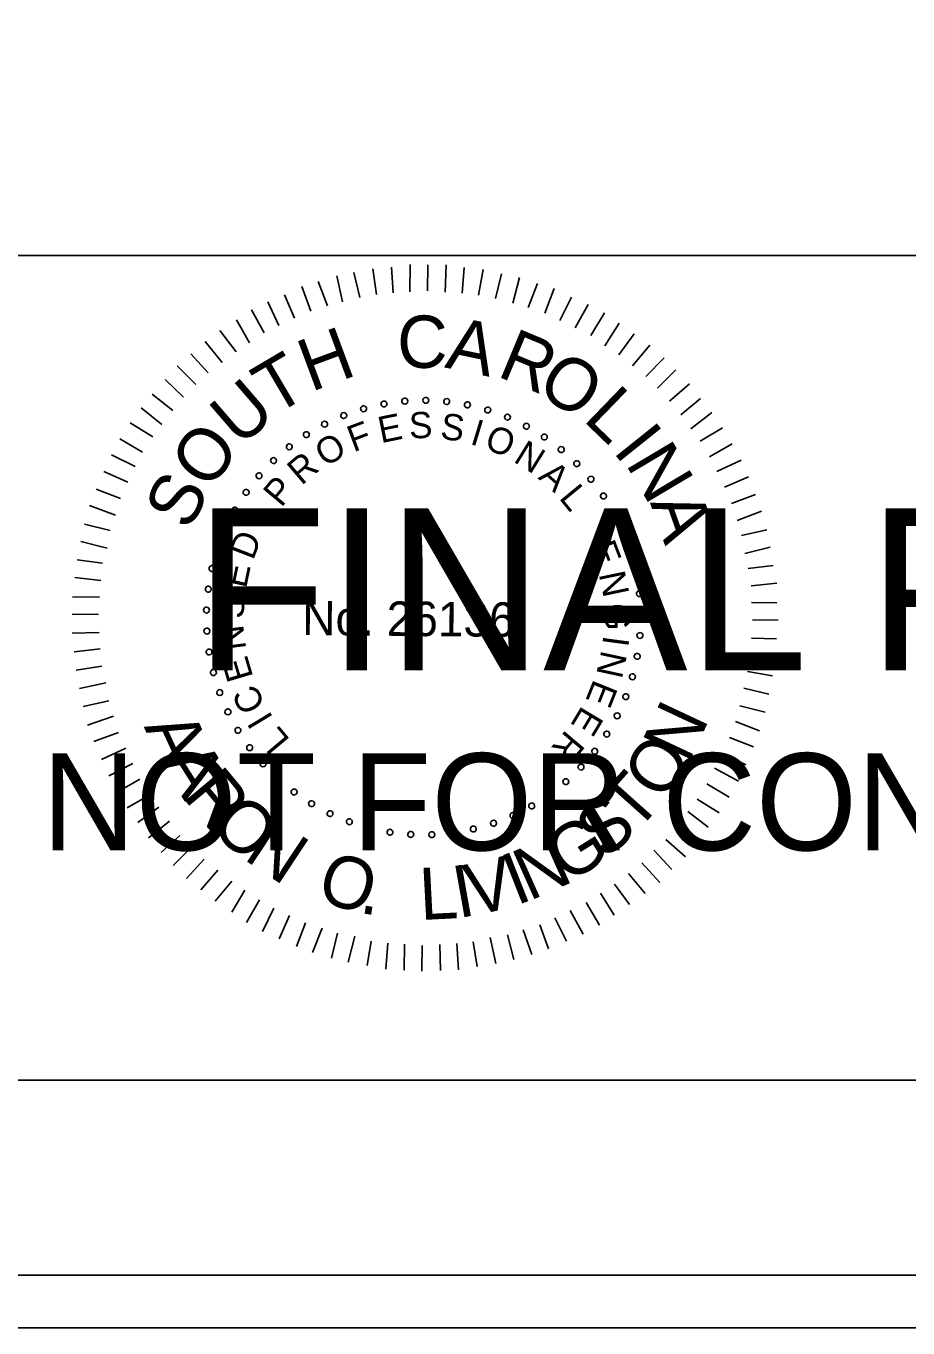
# Model space of a CAD drawing. Extents: x 967 to 1326, y 964 to 3704.
# Drawn here: x 1170.56 to 1189.3, y 3203.72 to 3231.36 of the extents above; entities that cross this region are included whole.
import ezdxf

# ---------------------------------------------------------------- set-up
doc = ezdxf.new("R2010")
doc.units = 0
for name, color, linetype in [('RD_SHT_Bndy', 7, 'Continuous'), ('RD_SHT_IplotShp', 7, 'Continuous'), ('RD_SHT_Misc1', 7, 'Continuous'), ('RD_SHT_Misc2', 7, 'Continuous'), ('RD_XS_TX_Station', 7, 'Continuous')]:
    doc.layers.add(name, color=color, linetype=linetype)

msp = doc.modelspace()

# ---------------------------------------------------------------- linework, layer by layer
at = {"layer": 'RD_SHT_Bndy'}
for p, q in [((996.114, 3226.486), (1323.886, 3226.486)), ((1323.886, 3208.983), (996.114, 3208.983))]:
    msp.add_line(p, q, dxfattribs=at)
at = {"layer": 'RD_SHT_IplotShp'}
for points in [[(967.409, 3203.72), (1326.285, 3203.72), (1326.285, 3423.72), (967.409, 3423.72)], [(988.525, 3204.84), (1326.285, 3204.84), (1326.285, 3422.6), (988.525, 3422.6)]]:
    msp.add_lwpolyline(points, close=True, dxfattribs=at)
at = {"layer": 'RD_SHT_Misc1'}
for p, q in [((1177.657, 3225.597), (1177.53, 3226.128)), ((1178.01, 3225.663), (1177.93, 3226.209)), ((1178.364, 3225.699), (1178.33, 3226.244)), ((1178.717, 3225.719), (1178.722, 3226.295)), ((1179.093, 3225.739), (1179.098, 3226.292)), ((1179.469, 3225.713), (1179.489, 3226.288)), ((1179.829, 3225.687), (1179.872, 3226.231)), ((1180.174, 3225.646), (1180.271, 3226.19)), ((1176.964, 3225.419), (1176.769, 3225.935)), ((1177.287, 3225.508), (1177.169, 3226.054)), ((1180.535, 3225.573), (1180.662, 3226.102)), ((1180.902, 3225.478), (1181.045, 3226.022)), ((1181.231, 3225.384), (1181.428, 3225.896)), ((1176.264, 3225.156), (1176.053, 3225.657)), ((1176.61, 3225.306), (1176.423, 3225.83)), ((1181.584, 3225.265), (1181.78, 3225.786)), ((1181.905, 3225.109), (1182.154, 3225.606)), ((1175.624, 3224.846), (1175.352, 3225.332)), ((1175.933, 3225.005), (1175.699, 3225.506)), ((1182.226, 3224.953), (1182.506, 3225.45)), ((1175.308, 3224.634), (1175.036, 3225.12)), ((1182.562, 3224.789), (1182.85, 3225.27)), ((1182.86, 3224.572), (1183.163, 3225.053)), ((1175.03, 3224.445), (1174.681, 3224.9)), ((1183.158, 3224.378), (1183.484, 3224.828)), ((1174.729, 3224.217), (1174.372, 3224.665)), ((1183.447, 3224.145), (1183.811, 3224.587)), ((1174.435, 3223.997), (1174.062, 3224.399)), ((1183.729, 3223.92), (1184.116, 3224.316)), ((1174.172, 3223.753), (1173.776, 3224.148)), ((1183.98, 3223.672), (1184.368, 3224.061)), ((1173.909, 3223.479), (1173.52, 3223.858)), ((1184.232, 3223.394), (1184.657, 3223.767)), ((1173.684, 3223.197), (1173.242, 3223.546)), ((1184.475, 3223.108), (1184.892, 3223.45)), ((1173.451, 3222.9), (1173.009, 3223.256)), ((1184.687, 3222.807), (1185.128, 3223.156)), ((1173.257, 3222.64), (1172.776, 3222.936)), ((1184.885, 3222.544), (1185.355, 3222.832)), ((1173.039, 3222.312), (1172.559, 3222.6)), ((1172.883, 3222.006), (1172.379, 3222.256)), ((1185.081, 3222.213), (1185.56, 3222.493)), ((1185.24, 3221.904), (1185.756, 3222.145)), ((1172.727, 3221.677), (1172.215, 3221.904)), ((1185.399, 3221.573), (1185.907, 3221.791)), ((1172.571, 3221.333), (1172.051, 3221.53)), ((1172.461, 3220.974), (1171.91, 3221.178)), ((1185.549, 3221.226), (1186.057, 3221.414)), ((1185.669, 3220.865), (1186.185, 3221.06)), ((1172.351, 3220.652), (1171.807, 3220.787)), ((1185.759, 3220.541), (1186.297, 3220.667)), ((1172.286, 3220.276), (1171.727, 3220.419)), ((1185.832, 3220.165), (1186.371, 3220.298)), ((1172.191, 3219.955), (1171.647, 3220.029)), ((1185.906, 3219.842), (1186.436, 3219.906)), ((1172.15, 3219.587), (1171.598, 3219.653)), ((1185.964, 3219.473), (1186.51, 3219.53)), ((1172.124, 3219.234), (1171.548, 3219.239)), ((1185.977, 3219.12), (1186.514, 3219.115)), ((1172.105, 3218.866), (1171.545, 3218.871)), ((1185.997, 3218.751), (1186.542, 3218.747)), ((1172.118, 3218.482), (1171.542, 3218.471)), ((1172.138, 3218.136), (1171.585, 3218.072)), ((1185.971, 3218.368), (1186.508, 3218.348)), ((1185.952, 3218.022), (1186.497, 3217.949)), ((1172.173, 3217.768), (1171.627, 3217.688)), ((1185.888, 3217.655), (1186.417, 3217.566)), ((1172.262, 3217.414), (1171.701, 3217.296)), ((1185.808, 3217.302), (1186.345, 3217.175)), ((1172.321, 3217.037), (1171.774, 3216.911)), ((1185.729, 3216.926), (1186.265, 3216.792)), ((1172.425, 3216.707), (1171.871, 3216.519)), ((1185.634, 3216.597), (1186.146, 3216.401)), ((1172.53, 3216.36), (1172.007, 3216.173)), ((1185.508, 3216.253), (1186.013, 3216.057)), ((1172.681, 3216.029), (1172.165, 3215.788)), ((1185.352, 3215.924), (1185.857, 3215.675)), ((1172.831, 3215.705), (1172.323, 3215.441)), ((1172.982, 3215.374), (1172.497, 3215.094)), ((1185.188, 3215.603), (1185.7, 3215.33)), ((1185.024, 3215.274), (1185.498, 3214.987)), ((1173.194, 3215.042), (1172.709, 3214.762)), ((1184.822, 3214.946), (1185.288, 3214.658)), ((1173.384, 3214.78), (1172.936, 3214.453)), ((1184.62, 3214.687), (1185.055, 3214.353)), ((1173.612, 3214.478), (1173.164, 3214.129)), ((1184.403, 3214.389), (1184.814, 3214.033)), ((1173.832, 3214.177), (1173.437, 3213.812)), ((1184.155, 3214.092), (1184.574, 3213.72)), ((1174.091, 3213.945), (1173.689, 3213.541)), ((1183.899, 3213.864), (1184.28, 3213.454)), ((1174.35, 3213.674), (1173.97, 3213.263)), ((1174.64, 3213.442), (1174.275, 3213.022)), ((1183.644, 3213.597), (1184.024, 3213.18)), ((1174.937, 3213.209), (1174.58, 3212.782)), ((1183.065, 3213.141), (1183.384, 3212.709)), ((1183.358, 3213.37), (1183.715, 3212.944)), ((1175.212, 3213.014), (1174.932, 3212.549)), ((1182.764, 3212.952), (1183.059, 3212.482)), ((1175.525, 3212.812), (1175.245, 3212.331)), ((1175.83, 3212.633), (1175.588, 3212.136)), ((1182.124, 3212.581), (1182.396, 3212.08)), ((1182.463, 3212.755), (1182.743, 3212.269)), ((1176.159, 3212.477), (1175.94, 3211.98)), ((1176.503, 3212.321), (1176.307, 3211.816)), ((1181.8, 3212.431), (1182.041, 3211.93)), ((1176.855, 3212.211), (1176.651, 3211.69)), ((1177.177, 3212.1), (1177.05, 3211.572)), ((1177.545, 3212.036), (1177.409, 3211.484)), ((1180.791, 3212.07), (1180.926, 3211.54)), ((1181.122, 3212.175), (1181.31, 3211.652)), ((1181.476, 3212.28), (1181.664, 3211.771)), ((1177.897, 3211.933), (1177.808, 3211.412)), ((1178.25, 3211.892), (1178.207, 3211.34)), ((1178.603, 3211.866), (1178.598, 3211.313)), ((1178.978, 3211.84), (1178.974, 3211.295)), ((1179.355, 3211.86), (1179.365, 3211.307)), ((1179.715, 3211.88), (1179.749, 3211.327)), ((1180.061, 3211.915), (1180.149, 3211.393)), ((1180.423, 3212.012), (1180.541, 3211.458))]:
    msp.add_line(p, q, dxfattribs=at)
for centre, start, end in [((1178.168, 3223.337), 10.6038, 190.6038), ((1178.168, 3223.337), 190.6038, 10.6038), ((1178.609, 3223.397), 5.0653, 185.0653), ((1178.609, 3223.397), 185.0653, 5.0653), ((1179.055, 3223.414), 359.5268, 179.5268), ((1179.055, 3223.414), 179.5268, 359.5268), ((1179.5, 3223.388), 353.9884, 173.9884), ((1179.5, 3223.388), 173.9884, 353.9884), ((1179.94, 3223.319), 348.4499, 168.4499), ((1177.312, 3223.091), 21.6807, 201.6807), ((1177.312, 3223.091), 201.6807, 21.6807), ((1177.734, 3223.235), 16.1422, 196.1422), ((1177.734, 3223.235), 196.1422, 16.1422), ((1179.94, 3223.319), 168.4499, 348.4499), ((1180.372, 3223.208), 162.9114, 342.9114), ((1180.372, 3223.208), 342.9114, 162.9114), ((1180.79, 3223.056), 157.373, 337.373), ((1180.79, 3223.056), 337.373, 157.373), ((1176.906, 3222.908), 27.2191, 207.2191), ((1176.906, 3222.908), 207.2191, 27.2191), ((1181.193, 3222.864), 151.8345, 331.8345), ((1181.193, 3222.864), 331.8345, 151.8345), ((1176.52, 3222.686), 32.7576, 212.7576), ((1176.52, 3222.686), 212.7576, 32.7576), ((1181.574, 3222.634), 146.2961, 326.2961), ((1181.574, 3222.634), 326.2961, 146.2961), ((1176.156, 3222.428), 38.2961, 218.2961), ((1176.156, 3222.428), 218.2961, 38.2961), ((1181.932, 3222.368), 140.7576, 320.7576), ((1181.932, 3222.368), 320.7576, 140.7576), ((1175.82, 3222.135), 43.8345, 223.8345), ((1175.82, 3222.135), 223.8345, 43.8345), ((1182.263, 3222.069), 135.2191, 315.2191), ((1182.263, 3222.069), 315.2191, 135.2191), ((1175.513, 3221.812), 49.373, 229.373), ((1175.513, 3221.812), 229.373, 49.373), ((1182.563, 3221.74), 129.6807, 309.6807), ((1182.563, 3221.74), 309.6807, 129.6807), ((1175.239, 3221.461), 54.9114, 234.9114), ((1175.239, 3221.461), 234.9114, 54.9114), ((1182.83, 3221.383), 124.1422, 304.1422), ((1182.83, 3221.383), 304.1422, 124.1422), ((1175, 3221.085), 60.4499, 240.4499), ((1175, 3221.085), 240.4499, 60.4499), ((1183.061, 3221.002), 118.6038, 298.6038), ((1183.061, 3221.002), 298.6038, 118.6038), ((1174.798, 3220.687), 65.9884, 245.9884), ((1174.798, 3220.687), 245.9884, 65.9884), ((1183.255, 3220.601), 113.0653, 293.0653), ((1183.255, 3220.601), 293.0653, 113.0653), ((1174.636, 3220.272), 71.5268, 251.5268), ((1174.636, 3220.272), 251.5268, 71.5268), ((1183.408, 3220.182), 107.5268, 287.5268), ((1183.408, 3220.182), 287.5268, 107.5268), ((1174.514, 3219.843), 77.0653, 257.0653), ((1174.514, 3219.843), 257.0653, 77.0653), ((1183.521, 3219.751), 101.9884, 281.9884), ((1183.521, 3219.751), 281.9884, 101.9884), ((1174.435, 3219.405), 82.6038, 262.6038), ((1174.435, 3219.405), 262.6038, 82.6038), ((1183.592, 3219.311), 96.4499, 276.4499), ((1183.592, 3219.311), 276.4499, 96.4499), ((1174.398, 3218.961), 88.1422, 268.1422), ((1174.398, 3218.961), 268.1422, 88.1422), ((1183.619, 3218.866), 90.9114, 270.9114), ((1183.619, 3218.866), 270.9114, 90.9114), ((1174.404, 3218.515), 93.6807, 273.6807), ((1174.404, 3218.515), 273.6807, 93.6807), ((1183.604, 3218.421), 85.373, 265.373), ((1183.604, 3218.421), 265.373, 85.373), ((1174.453, 3218.072), 99.2191, 279.2191), ((1174.453, 3218.072), 279.2191, 99.2191), ((1183.546, 3217.979), 79.8345, 259.8345), ((1183.546, 3217.979), 259.8345, 79.8345), ((1174.545, 3217.636), 104.7576, 284.7576), ((1174.545, 3217.636), 284.7576, 104.7576), ((1183.445, 3217.545), 74.2961, 254.2961), ((1183.445, 3217.545), 254.2961, 74.2961), ((1174.678, 3217.211), 110.2961, 290.2961), ((1174.678, 3217.211), 290.2961, 110.2961), ((1183.303, 3217.122), 68.7576, 248.7576), ((1183.303, 3217.122), 248.7576, 68.7576), ((1174.852, 3216.8), 115.8345, 295.8345), ((1174.852, 3216.8), 295.8345, 115.8345), ((1183.121, 3216.716), 63.2191, 243.2191), ((1183.121, 3216.716), 243.2191, 63.2191), ((1175.065, 3216.409), 121.373, 301.373), ((1175.065, 3216.409), 301.373, 121.373), ((1182.9, 3216.328), 57.6807, 237.6807), ((1182.9, 3216.328), 237.6807, 57.6807), ((1175.314, 3216.039), 126.9114, 306.9114), ((1175.314, 3216.039), 306.9114, 126.9114), ((1182.643, 3215.964), 52.1422, 232.1422), ((1182.643, 3215.964), 232.1422, 52.1422), ((1175.598, 3215.696), 132.4499, 312.4499), ((1175.598, 3215.696), 312.4499, 132.4499), ((1182.353, 3215.627), 46.6038, 226.6038), ((1182.353, 3215.627), 226.6038, 46.6038), ((1175.914, 3215.381), 137.9884, 317.9884), ((1175.914, 3215.381), 317.9884, 137.9884), ((1182.03, 3215.319), 41.0653, 221.0653), ((1182.03, 3215.319), 221.0653, 41.0653), ((1176.258, 3215.099), 143.5268, 323.5268), ((1176.258, 3215.099), 323.5268, 143.5268), ((1181.68, 3215.043), 35.5268, 215.5268), ((1181.68, 3215.043), 215.5268, 35.5268), ((1176.629, 3214.851), 149.0653, 329.0653), ((1176.629, 3214.851), 329.0653, 149.0653), ((1181.305, 3214.803), 29.9884, 209.9884), ((1181.305, 3214.803), 209.9884, 29.9884), ((1177.021, 3214.639), 154.6038, 334.6038), ((1177.021, 3214.639), 334.6038, 154.6038), ((1177.432, 3214.467), 340.1422, 160.1422), ((1180.908, 3214.6), 24.4499, 204.4499), ((1180.908, 3214.6), 204.4499, 24.4499), ((1177.432, 3214.467), 160.1422, 340.1422), ((1177.858, 3214.335), 165.6807, 345.6807), ((1177.858, 3214.335), 345.6807, 165.6807), ((1178.294, 3214.245), 351.2191, 171.2191), ((1178.294, 3214.245), 171.2191, 351.2191), ((1178.737, 3214.198), 356.7576, 176.7576), ((1179.183, 3214.193), 2.2961, 182.2961), ((1179.627, 3214.232), 7.8345, 187.8345), ((1179.627, 3214.232), 187.8345, 7.8345), ((1180.065, 3214.313), 13.373, 193.373), ((1180.065, 3214.313), 193.373, 13.373), ((1180.494, 3214.436), 18.9114, 198.9114), ((1180.494, 3214.436), 198.9114, 18.9114), ((1178.737, 3214.198), 176.7576, 356.7576), ((1179.183, 3214.193), 182.2961, 2.2961)]:
    msp.add_arc(centre, 0.0627, start, end, dxfattribs=at)
at = {"layer": 'RD_XS_TX_Station'}
msp.add_lwpolyline([(967.409, 3203.72), (1326.285, 3203.72), (1326.285, 3423.72), (967.409, 3423.72)], close=True, dxfattribs=at)

# ---------------------------------------------------------------- texts
at = {"layer": 'RD_SHT_Misc1'}
for s, height, rotation, p in [('C', 1.11, 359.5482, (1178.442, 3224.108)), ('A', 1.11, 348.1981, (1179.439, 3224.115)), ('H', 1.11, 20.3637, (1176.614, 3223.587)), ('R', 1.11, 337.4344, (1180.541, 3223.937)), ('T', 1.11, 30.4992, (1175.828, 3223.072)), ('O', 1.108, 326.5869, (1181.366, 3223.609)), ('U', 1.11, 40.8022, (1175.102, 3222.403)), ('L', 1.11, 315.9488, (1182.373, 3223.003)), ('E', 0.557, 11.4103, (1178.103, 3222.503)), ('S', 0.557, 2.208, (1178.709, 3222.601)), ('S', 0.557, 352.6608, (1179.346, 3222.599)), ('O', 1.11, 52.0267, (1174.435, 3221.474)), ('F', 0.557, 20.6127, (1177.52, 3222.309)), ('I', 0.557, 343.1136, (1179.975, 3222.491)), ('O', 0.557, 338.4392, (1180.274, 3222.401)), ('I', 1.11, 308.6613, (1183.011, 3222.338)), ('O', 0.557, 30.8477, (1176.917, 3221.987)), ('N', 0.557, 328.2042, (1180.896, 3222.12)), ('N', 1.11, 300.7037, (1183.285, 3222.075)), ('R', 0.557, 40.3949, (1176.415, 3221.594)), ('A', 0.557, 318.657, (1181.424, 3221.762)), ('S', 1.108, 63.2511, (1174.029, 3220.619)), ('P', 0.557, 49.9421, (1175.985, 3221.124)), ('L', 0.557, 309.4546, (1181.869, 3221.339)), ('A', 1.11, 289.4792, (1183.814, 3221.243)), ('D', 0.557, 69.0364, (1175.386, 3220.003)), ('E', 0.557, 291.049, (1182.53, 3220.307)), ('E', 0.557, 78.2388, (1175.238, 3219.407)), ('N', 0.557, 281.8466, (1182.728, 3219.726)), ('S', 0.557, 87.786, (1175.187, 3218.772)), ('No. 26136', 0.7311, 359.5268, (1176.429, 3218.43)), ('G', 0.557, 272.2995, (1182.833, 3219.097)), ('N', 0.557, 97.3332, (1175.242, 3218.137)), ('I', 0.557, 262.4084, (1182.83, 3218.437)), ('E', 0.557, 106.5355, (1175.394, 3217.541)), ('N', 0.557, 257.7339, (1182.789, 3218.127)), ('C', 0.557, 116.4266, (1175.661, 3216.938)), ('E', 0.557, 248.1867, (1182.628, 3217.511)), ('N', 1.105, 64.8922, (1184.632, 3215.684)), ('I', 0.557, 121.1011, (1175.823, 3216.67)), ('E', 0.557, 238.9844, (1182.378, 3216.949)), ('A', 1.105, 294.7297, (1173.062, 3216.486)), ('L', 0.557, 129.9595, (1176.187, 3216.204)), ('R', 0.557, 229.782, (1182.041, 3216.435)), ('O', 1.105, 56.2059, (1184.102, 3214.874)), ('A', 1.105, 302.2892, (1173.414, 3215.72)), ('R', 1.105, 309.8487, (1173.865, 3215.007)), ('T', 1.105, 48.2685, (1183.515, 3214.211)), ('O', 1.105, 317.7861, (1174.434, 3214.33)), ('S', 1.105, 40.3311, (1182.842, 3213.636)), ('N', 1.105, 326.4725, (1175.158, 3213.686)), ('G', 1.105, 32.0198, (1182.059, 3213.14)), ('N', 1.105, 24.0824, (1181.252, 3212.776)), ('O', 1.105, 342.3472, (1176.697, 3212.82)), ('V', 1.105, 12.7741, (1180.033, 3212.457)), ('I', 1.105, 21.4605, (1180.976, 3212.681)), ('L', 1.105, 2.9677, (1178.943, 3212.379)), ('I', 1.105, 10.1523, (1179.743, 3212.418)), ('.', 1.105, 351.0336, (1177.623, 3212.536))]:
    msp.add_text(s, height=height, rotation=rotation, dxfattribs=at).set_placement(p)
at = {"layer": 'RD_SHT_Misc2'}
for s, height, p in [('FINAL PLANS', 3.4375, (1174.145, 3217.685)), ('NOT FOR CONSTRUCTION', 2.0625, (1170.901, 3213.86))]:
    msp.add_text(s, height=height, dxfattribs=at).set_placement(p)

doc.saveas('drawing.dxf')
